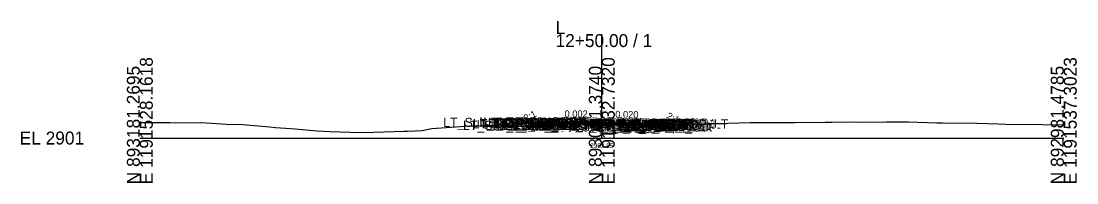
# Model space of a CAD drawing. Extents: x -26 to 203, y -10 to 7027.
# Drawn here: x -25.7 to 202.8, y 4990.3 to 5025.3 of the extents above; entities that cross this region are included whole.
import ezdxf

# ---------------------------------------------------------------- set-up
doc = ezdxf.new("R2010")
doc.units = 0
for name, color, linetype in [('Default', 7, 'Continuous'), ('Exist CMT Pavement', 7, 'Continuous'), ('Exist Cross Section Cell', 7, 'Continuous'), ('Exist XS Center Line Elevation Label', 7, 'Continuous'), ('Exist XS Ground Line', 7, 'Continuous'), ('Prop CMT Concrete Structures', 7, 'Continuous'), ('Prop CMT Pvmt Course 1', 7, 'Continuous'), ('Prop CMT Pvmt Course 2', 7, 'Continuous'), ('Prop CMT Pvmt Course 2 Wedge', 7, 'Continuous'), ('Prop CMT Pvmt Course 3', 7, 'Continuous'), ('Prop CMT Pvmt Course 3 Wedge', 7, 'Continuous'), ('Prop CMT Pvmt Surface', 7, 'Continuous'), ('Prop CMT Pvmt Surface Shoulder', 7, 'Continuous'), ('Prop CMT Pvmt Wedge Surface 3', 7, 'Continuous'), ('Prop CMT Shld Paved Course 1', 7, 'Continuous'), ('Prop CMT Shld Paved Course 2', 7, 'Continuous'), ('Prop CMT Shld Paved Course 3', 7, 'Continuous'), ('Prop CMT Slope Grass', 7, 'Continuous'), ('Prop CMT Subgrade Earthwork', 7, 'Continuous'), ('Scratch_Level_6', 7, 'Continuous')]:
    doc.layers.add(name, color=color, linetype=linetype)

msp = doc.modelspace()

# ---------------------------------------------------------------- linework, layer by layer
at = {"layer": 'Exist CMT Pavement'}
for points in [[(89, 5003.28), (86.79, 5003.28), (86.58, 5003.08)], [(86.58, 5003.08), (89, 5003.07)], [(89, 5003.07), (89, 5003.28)], [(100, 5002.85), (89, 5003.09)], [(89, 5003.09), (94.5, 5002.94)], [(94.5, 5002.94), (100, 5002.85)], [(104.41, 5002.78), (100, 5002.85)], [(100, 5002.85), (108.83, 5002.73)], [(108.83, 5002.73), (104.41, 5002.78)], [(111, 5003.03), (113.21, 5002.99), (113.43, 5002.77)], [(111, 5002.82), (111, 5003.03)], [(113.43, 5002.77), (111, 5002.82)]]:
    msp.add_lwpolyline(points, dxfattribs=at)
at = {"layer": 'Exist Cross Section Cell'}
for p, q in [((100, 5000), (100, 5022.47)), ((0, 5000), (100, 5000)), ((100, 5000), (200, 5000))]:
    msp.add_line(p, q, dxfattribs=at)
at = {"layer": 'Exist XS Center Line Elevation Label'}
for points in [[(100, 5003.25), (89, 5003.28)], [(100, 5003.25), (108.83, 5003.08)]]:
    msp.add_lwpolyline(points, dxfattribs=at)
at = {"layer": 'Exist XS Ground Line'}
for points in [[(100, 5003.34), (89, 5003.36)], [(100, 5003.34), (108.83, 5003.16)]]:
    msp.add_lwpolyline(points, dxfattribs=at)
at = {"layer": 'Prop CMT Concrete Structures'}
for points in [[(100, 5003.46), (89, 5003.49)], [(100, 5003.46), (111, 5003.24)]]:
    msp.add_lwpolyline(points, dxfattribs=at)
at = {"layer": 'Prop CMT Pvmt Course 1'}
for points in [[(100, 5003.46), (89, 5003.49)], [(89, 5003.49), (89, 5003.28), (89, 5003.28), (89, 5003.36)], [(89, 5003.36), (100, 5003.34)], [(89, 5003.07), (89, 5003.07), (89, 5003.28), (89, 5003.28)], [(89, 5003.28), (89, 5003.07)], [(100, 5003.25), (100, 5003.46)], [(100, 5003.46), (111, 5003.24)], [(100, 5003.25), (100, 5003.46)], [(100, 5003.34), (100, 5003.25), (100, 5003.25)], [(108.83, 5003.16), (100, 5003.34)], [(100, 5003.34), (100, 5003.25), (100, 5003.25)], [(108.83, 5003.08), (108.83, 5003.16)], [(111, 5003.03), (108.83, 5003.08)], [(108.83, 5002.87), (108.83, 5003.08)], [(108.83, 5003.08), (111, 5003.03)], [(111, 5002.82), (108.83, 5002.87)], [(111, 5003.24), (111, 5003.03)], [(111, 5003.03), (111, 5002.82)]]:
    msp.add_lwpolyline(points, dxfattribs=at)
at = {"layer": 'Prop CMT Pvmt Course 2'}
for points in [[(100, 5003.04), (89, 5003.07)], [(100, 5003.04), (108.83, 5002.87)]]:
    msp.add_lwpolyline(points, dxfattribs=at)
at = {"layer": 'Prop CMT Pvmt Course 3'}
for points in [[(89, 5003.07), (89, 5003.07), (89, 5002.74), (89, 5002.74)], [(89, 5002.74), (89, 5003.07)], [(108.83, 5002.87), (111, 5002.82)], [(108.83, 5002.53), (108.83, 5002.87)], [(111, 5002.82), (111, 5002.49)], [(111, 5002.49), (108.83, 5002.53)]]:
    msp.add_lwpolyline(points, dxfattribs=at)
at = {"layer": 'Prop CMT Pvmt Course 3 Wedge'}
for p, q in [((0, 5003.39), (5.82, 5003.33)), ((5.82, 5003.33), (6.57, 5003.33)), ((6.57, 5003.33), (7.61, 5003.26)), ((7.61, 5003.26), (13.34, 5003.33)), ((13.34, 5003.33), (18.75, 5003)), ((18.75, 5003), (22.26, 5002.91)), ((22.26, 5002.91), (28.17, 5002.4)), ((63.24, 5002.07), (71.41, 5002.62)), ((71.41, 5002.62), (72.3, 5002.63)), ((72.3, 5002.63), (80.29, 5002.84)), ((80.29, 5002.84), (81.16, 5002.77)), ((81.16, 5002.77), (82.13, 5002.98)), ((82.13, 5002.98), (83.39, 5003.13)), ((83.39, 5003.13), (87.73, 5003.65)), ((87.73, 5003.65), (88.19, 5003.13)), ((88.19, 5003.13), (88.55, 5003.12)), ((88.55, 5003.12), (90.71, 5003)), ((90.71, 5003), (91.38, 5002.99)), ((91.38, 5002.99), (96.15, 5002.91)), ((96.15, 5002.91), (99.5, 5002.86)), ((99.5, 5002.86), (100, 5002.85)), ((100, 5002.85), (100.76, 5002.83)), ((100.76, 5002.83), (108.83, 5002.73)), ((108.83, 5002.73), (109.53, 5002.61)), ((109.53, 5002.61), (111.11, 5002.53)), ((111.11, 5002.53), (112.55, 5002.66)), ((112.55, 5002.66), (112.96, 5002.71)), ((112.96, 5002.71), (113.92, 5002.77)), ((113.92, 5002.77), (116.91, 5002.57)), ((116.91, 5002.57), (122.89, 5003.12)), ((122.89, 5003.12), (126.9, 5003.17)), ((126.9, 5003.17), (127.31, 5003.18)), ((127.31, 5003.18), (132.13, 5003.34)), ((132.13, 5003.34), (137.05, 5003.39)), ((137.05, 5003.39), (137.67, 5003.39)), ((137.67, 5003.39), (141.85, 5003.38)), ((141.85, 5003.38), (148.32, 5003.45)), ((148.32, 5003.45), (149.76, 5003.42)), ((149.76, 5003.42), (153.72, 5003.47)), ((153.72, 5003.47), (155.56, 5003.44)), ((155.56, 5003.44), (161.64, 5003.51)), ((161.64, 5003.51), (164.29, 5003.51)), ((164.29, 5003.51), (166.01, 5003.49)), ((166.01, 5003.49), (166.39, 5003.5)), ((166.39, 5003.5), (172.53, 5003.27)), ((172.53, 5003.27), (173.28, 5003.27)), ((173.28, 5003.27), (173.75, 5003.25)), ((173.75, 5003.25), (181.15, 5003.23)), ((181.15, 5003.23), (185.85, 5003.08)), ((185.85, 5003.08), (187.38, 5003)), ((187.38, 5003), (195.34, 5002.94)), ((195.34, 5002.94), (199.59, 5002.84)), ((199.59, 5002.84), (200, 5002.83)), ((28.17, 5002.4), (29.37, 5002.26)), ((29.37, 5002.26), (32.65, 5002.05)), ((32.65, 5002.05), (33.6, 5001.98)), ((33.6, 5001.98), (38.38, 5001.53)), ((38.38, 5001.53), (41.12, 5001.44)), ((41.12, 5001.44), (45.6, 5001.28)), ((45.6, 5001.28), (48.52, 5001.17)), ((48.52, 5001.17), (57.17, 5001.47)), ((57.17, 5001.47), (57.92, 5001.48)), ((57.92, 5001.48), (61.1, 5001.62)), ((61.1, 5001.62), (63.24, 5002.07))]:
    msp.add_line(p, q, dxfattribs=at)
at = {"layer": 'Prop CMT Pvmt Surface'}
for points in [[(87, 5003.49), (85, 5003.38), (84.86, 5003.31)], [(113, 5003.2), (115, 5003.04), (115.79, 5002.64)]]:
    msp.add_lwpolyline(points, dxfattribs=at)
at = {"layer": 'Prop CMT Pvmt Surface Shoulder'}
for points in [[(89, 5003.49), (87, 5003.49)], [(111, 5003.24), (113, 5003.2)]]:
    msp.add_lwpolyline(points, dxfattribs=at)
at = {"layer": 'Prop CMT Shld Paved Course 1'}
for points in [[(89, 5003.49), (87, 5003.49), (86.79, 5003.28)], [(86.79, 5003.28), (89, 5003.28)], [(89, 5003.28), (89, 5003.49)], [(89, 5003.28), (89, 5003.49)], [(100, 5003.34), (89, 5003.36)], [(89, 5003.36), (89, 5003.28), (89, 5003.28)], [(100, 5003.34), (108.83, 5003.16)], [(108.83, 5003.16), (108.83, 5003.08)], [(108.83, 5003.08), (111, 5003.03)], [(111, 5003.24), (113, 5003.2), (113.21, 5002.99)], [(111, 5003.03), (111, 5003.24)], [(111, 5003.03), (111, 5003.24)], [(113.21, 5002.99), (111, 5003.03)]]:
    msp.add_lwpolyline(points, dxfattribs=at)
at = {"layer": 'Prop CMT Shld Paved Course 2'}
for points in [[(89, 5003.28), (89, 5003.49)], [(100, 5003.25), (89, 5003.28)], [(100, 5003.25), (111, 5003.03)], [(111, 5003.03), (111, 5003.24)]]:
    msp.add_lwpolyline(points, dxfattribs=at)
at = {"layer": 'Prop CMT Shld Paved Course 3'}
for points in [[(89, 5003.07), (89, 5003.49)], [(100, 5003.04), (89, 5003.07)], [(100, 5003.04), (111, 5002.82)], [(111, 5002.82), (111, 5003.24)]]:
    msp.add_lwpolyline(points, dxfattribs=at)
at = {"layer": 'Prop CMT Slope Grass'}
for points in [[(89, 5003.07), (86.58, 5003.08), (86.08, 5003.08), (85.75, 5002.75)], [(85.75, 5002.75), (89, 5002.74)], [(89, 5002.74), (89, 5003.07)], [(111, 5002.82), (113.43, 5002.77), (113.93, 5002.76), (114.27, 5002.42)], [(111, 5002.49), (111, 5002.82)], [(114.27, 5002.42), (111, 5002.49)]]:
    msp.add_lwpolyline(points, dxfattribs=at)
at = {"layer": 'Prop CMT Subgrade Earthwork'}
for points in [[(85.75, 5002.75), (85.11, 5003.38)], [(89, 5002.74), (85.75, 5002.75)], [(89, 5002.74), (89.02, 5003.09)], [(89, 5002.74), (89, 5002.74)], [(108.83, 5002.53), (108.81, 5002.73)], [(114.27, 5002.42), (114.89, 5003.05)], [(108.83, 5002.53), (111, 5002.49)], [(111, 5002.49), (114.27, 5002.42)]]:
    msp.add_lwpolyline(points, dxfattribs=at)

# ---------------------------------------------------------------- texts
at = {"layer": 'Default'}
msp.add_text('-', height=0.0001, dxfattribs=at).set_placement((0, 5000))
at = {"layer": 'Exist Cross Section Cell'}
for s, p in [('L', (90, 5022.47)), ('12+50.00 / 1', (90, 5019.67)), ('EL 2901', (-26, 4998.6))]:
    msp.add_text(s, height=2.8, dxfattribs=at).set_placement(p)
for s, p in [('E 1191528.1618', (2.8, 4990)), ('E 1191532.7320', (102.8, 4990)), ('E 1191537.3023', (202.8, 4990)), ('N 893181.2695', (0, 4990)), ('N 893081.3740', (100, 4990)), ('N 892981.4785', (200, 4990))]:
    msp.add_text(s, height=2.8, rotation=90, dxfattribs=at).set_placement(p)
at = {"layer": 'Prop CMT Pvmt Course 2 Wedge'}
for s, p in [('LT_Sub_Trench_Out_DLT', (65.68, 5002.38)), ('LT_Sub_Trench_Out', (69.96, 5001.75)), ('LT_PS3_Shelf_Out', (72.07, 5002.08)), ('LT_PV_Sub_Tie_Out', (73.96, 5002.09)), ('LT_GS_OS_CTL', (74.37, 5002.38)), ('LT_Slope_Fill', (75.38, 5002.31)), ('LT_PV_OEEOP_EG', (76.54, 5002.09)), ('LT_PS3_OEOP', (76.82, 5002.08)), ('LT_PS2_OEOP', (77.03, 5002.28)), ('LT_PS1_OEOP', (77.8, 5002.49)), ('LT_Sub_OEEOP', (78.21, 5001.74)), ('LT_PV2_OEEOP', (78.31, 5002.28)), ('LT_PV3_OEEOP', (78.31, 5002.07)), ('LT_PV1_OEEOP', (78.87, 5002.36)), ('LT_Sub_OEOT', (79.08, 5001.74)), ('LT_PV2_OEOT', (79.17, 5002.28)), ('LT_PV3_OEOT', (79.17, 5002.07)), ('LT_PV1_OEOT', (79.74, 5002.49)), ('LT_PV_EG_TestPt', (80.91, 5001.94)), ('RT_PV_IEEOP_EG', (88.14, 5001.85)), ('LT_PV_IEEOP_EG', (88.19, 5001.85)), ('RT_PV2_IEEOP', (89.91, 5002.25)), ('RT_PV3_IEEOP', (89.91, 5002.04)), ('LT_PV2_IEEOP', (89.95, 5002.25)), ('LT_PV3_IEEOP', (89.95, 5002.04)), ('RT_PV1_IEEOP', (90.47, 5002.34)), ('LT_PV1_IEEOP', (90.52, 5002.34)), ('RT_PV_EG_TestPt', (90.78, 5001.78)), ('RT_PV_Sub_Tie_Out', (93.71, 5001.73)), ('PV2_PGL', (93.91, 5002.25)), ('PV1_PGL', (94.47, 5002.46)), ('RT_Sub_Trench_Out_DLT', (95.41, 5002.05)), ('RT_PV_OEEOP_EG', (96.33, 5001.73)), ('RT_Sub_OEEOP', (97.99, 5001.53)), ('RT_PV2_OEEOP', (98.09, 5002.08)), ('RT_PV3_OEEOP', (98.09, 5001.87)), ('RT_Sub_Trench_Out', (98.42, 5001.42)), ('RT_PV1_OEEOP', (98.66, 5002.16)), ('RT_PS3_Shelf_Out', (99.86, 5001.76)), ('RT_Sub_OEOT', (101.03, 5001.49)), ('RT_PV2_OEOT', (101.13, 5002.03)), ('RT_PV3_OEOT', (101.13, 5001.82)), ('RT_PV1_OEOT', (101.69, 5002.24)), ('RT_PS2_OEOP', (103.4, 5001.99)), ('RT_PS3_OEOP', (103.61, 5001.77)), ('RT_PS1_OEOP', (103.76, 5002.2)), ('RT_GS_OS_CTL', (104.32, 5002.04)), ('RT_Slope_Fill', (106.27, 5001.64))]:
    msp.add_text(s, height=2, dxfattribs=at).set_placement(p)
at = {"layer": 'Prop CMT Pvmt Surface Shoulder'}
for s, rotation, p in [('0.002', 359.8568, (91.94, 5004.48)), ('0.020', 358.8542, (102.9, 5004.4))]:
    msp.add_text(s, height=1.5, rotation=rotation, dxfattribs=at).set_placement(p)
at = {"layer": 'Prop CMT Pvmt Wedge Surface 3'}
for rotation, p in [(26.5651, (83.53, 5003.48)), (333.4349, (113.86, 5004.31))]:
    msp.add_text('2:1', height=1.5, rotation=rotation, dxfattribs=at).set_placement(p)
at = {"layer": 'Scratch_Level_6'}
msp.add_text('2903.85', height=1, dxfattribs=at).set_placement((97.5, 4997.85))

doc.saveas('drawing.dxf')
